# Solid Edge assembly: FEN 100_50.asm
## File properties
Title: Zylinder
Author: bmolnar
Template: iso assembly.asm
Last saved by: bmolnar
Revision: 12
Application: Solid Edge
Username: bmolnar
Dokumentum tartalom típus: 1
Document Number: FEN 100/50
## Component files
Kolbenstange.par
Profilrohr.par
Kit_1.par
Kit_2.par
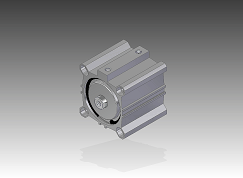
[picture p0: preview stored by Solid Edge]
